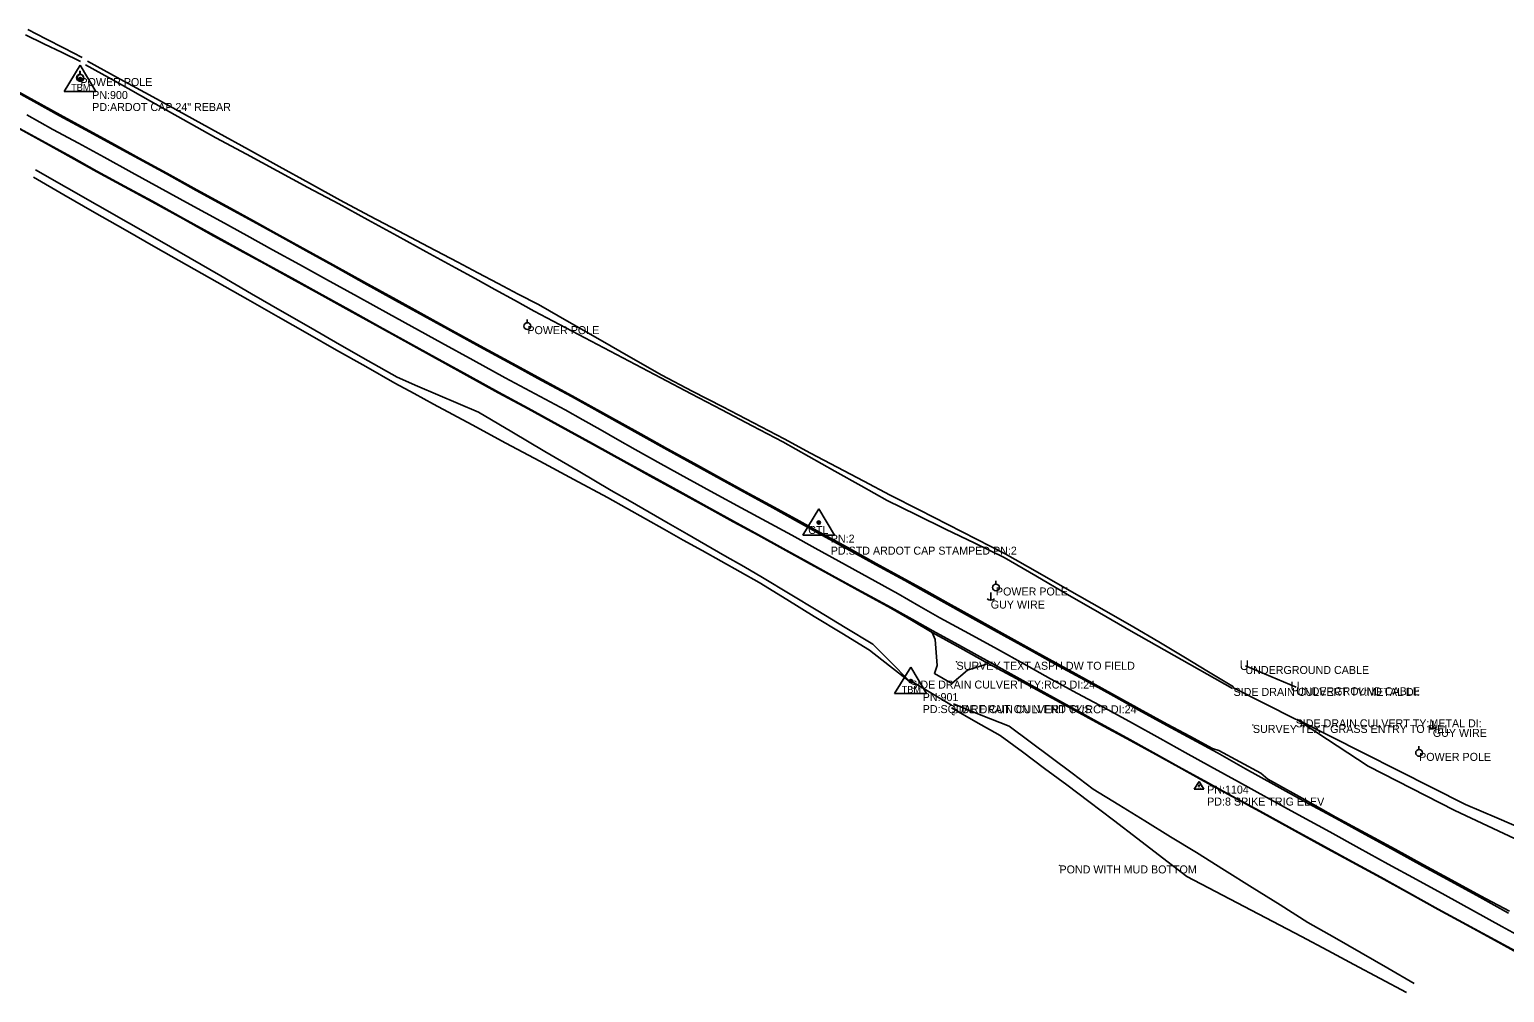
# Model space of a CAD drawing. Extents: x 1411444 to 1458157, y 300965 to 327300.
# Drawn here: x 1453733 to 1454655, y 302804 to 303406 of the extents above; entities that cross this region are included whole.
import ezdxf

# ---------------------------------------------------------------- set-up
doc = ezdxf.new("R2010")
doc.units = 0
for name, color, linetype in [('S_DITCHLINE', 7, 'Continuous'), ('S_DRG_PT_SYM', 7, 'Continuous'), ('S_DRIVEWAY', 7, 'Continuous'), ('S_EDGE_PAVEMENT', 7, 'Continuous'), ('S_MSC_PT_SYM', 7, 'Continuous'), ('S_PAVEMENT_CROWN', 7, 'Continuous'), ('S_PRIMARY_CTL', 7, 'Continuous'), ('S_PRIMARY_CTL_ANNOT', 7, 'Continuous'), ('S_SECONDARY_CTL', 7, 'Continuous'), ('S_SECONDARY_CTL_ANNOT', 7, 'Continuous'), ('S_SHOULDER', 7, 'Continuous'), ('S_SIDE_DRAIN', 7, 'Continuous'), ('S_SIDE_DRAIN_ANNOT', 7, 'Continuous'), ('S_SURVEY_TEXT_ANNOT', 7, 'Continuous'), ('S_UNDERGROUND_CABLE', 7, 'Continuous'), ('S_UNDERGROUND_CABLE_ANNOT', 7, 'Continuous'), ('S_UTILITY_POLE', 7, 'Continuous'), ('S_UTILITY_POLE_ANNOT', 7, 'Continuous'), ('S_UTL_PT_SYM', 7, 'Continuous')]:
    doc.layers.add(name, color=color, linetype=linetype)

msp = doc.modelspace()

# ---------------------------------------------------------------- linework, layer by layer
at = {"layer": 'S_DITCHLINE'}
for points in [[(1453730.77, 303402.44), (1453742.23, 303396.89), (1453753.69, 303391.35), (1453765.15, 303385.8)], [(1453732.25, 303405.79), (1453743.57, 303399.94), (1453754.89, 303394.08), (1453766.21, 303388.22)], [(1453768.3, 303383.8), (1453788.63, 303372.38), (1453808.97, 303360.95), (1453829.3, 303349.52), (1453849.63, 303338.09), (1453868.85, 303327.78), (1453888.08, 303317.46), (1453907.3, 303307.14), (1453926.52, 303296.82), (1453944.74, 303286.85), (1453962.97, 303276.87), (1453981.2, 303266.9), (1453999.42, 303256.92), (1454011.73, 303250.13), (1454024.04, 303243.33), (1454036.36, 303236.53), (1454048.67, 303229.74), (1454068.46, 303219.32), (1454088.25, 303208.9), (1454108.04, 303198.48), (1454127.83, 303188.06), (1454146.88, 303178.05), (1454165.93, 303168.04), (1454184.98, 303158.02), (1454204.03, 303148.01), (1454220.35, 303138.84), (1454236.68, 303129.68), (1454253, 303120.51), (1454269.32, 303111.34), (1454287.57, 303102.45), (1454305.82, 303093.57), (1454324.08, 303084.68), (1454342.33, 303075.79), (1454362.21, 303064.26), (1454382.09, 303052.73), (1454401.97, 303041.19), (1454421.85, 303029.66), (1454437.66, 303020.73), (1454453.47, 303011.8), (1454469.29, 303002.86), (1454485.1, 302993.93)], [(1453769.49, 303386.06), (1453789.92, 303374.85), (1453810.34, 303363.64), (1453830.76, 303352.42), (1453851.18, 303341.21), (1453870.24, 303330.69), (1453889.29, 303320.17), (1453908.34, 303309.66), (1453927.4, 303299.14), (1453945.78, 303289.43), (1453964.17, 303279.71), (1453982.56, 303270), (1454000.95, 303260.29), (1454013.55, 303253.68), (1454026.16, 303247.07), (1454038.76, 303240.47), (1454051.37, 303233.86), (1454070.63, 303222.86), (1454089.88, 303211.85), (1454109.14, 303200.84), (1454128.4, 303189.84), (1454147.51, 303179.85), (1454166.63, 303169.86), (1454185.74, 303159.87), (1454204.85, 303149.88), (1454221.45, 303141.09), (1454238.06, 303132.29), (1454254.66, 303123.5), (1454271.26, 303114.7), (1454289.23, 303105.52), (1454307.2, 303096.35), (1454325.17, 303087.17), (1454343.14, 303077.99), (1454363.24, 303066.57), (1454383.33, 303055.16), (1454403.42, 303043.75), (1454423.51, 303032.33), (1454439.08, 303022.98), (1454454.64, 303013.64), (1454470.21, 303004.29), (1454485.77, 302994.94)], [(1453735.71, 303313.45), (1453754.82, 303302.48), (1453773.93, 303291.52), (1453793.05, 303280.55), (1453812.16, 303269.59), (1453831.32, 303258.72), (1453850.48, 303247.86), (1453869.64, 303237), (1453888.79, 303226.14), (1453907.02, 303215.79), (1453925.24, 303205.44), (1453943.46, 303195.1), (1453961.68, 303184.75), (1453973.74, 303178.24), (1453985.79, 303171.72), (1453997.84, 303165.21), (1454009.9, 303158.69), (1454031.07, 303147.33), (1454052.23, 303135.97), (1454073.4, 303124.6), (1454094.56, 303113.24), (1454106.4, 303106.61), (1454118.23, 303099.98), (1454130.06, 303093.35), (1454141.89, 303086.72), (1454153.72, 303080.09), (1454165.56, 303073.46), (1454177.39, 303066.83), (1454189.22, 303060.2), (1454206.5, 303049.6), (1454223.78, 303039), (1454241.07, 303028.41), (1454258.35, 303017.81), (1454270.74, 303008.15), (1454283.14, 302998.49)], [(1453737.12, 303318.1), (1453756.48, 303307.07), (1453775.84, 303296.04), (1453795.2, 303285), (1453814.56, 303273.97), (1453833.71, 303262.86), (1453852.86, 303251.74), (1453872.01, 303240.63), (1453891.16, 303229.52), (1453909.11, 303219.24), (1453927.07, 303208.97), (1453945.02, 303198.69), (1453962.97, 303188.42), (1453975.72, 303182.95), (1453988.47, 303177.49), (1454001.22, 303172.02), (1454013.97, 303166.56), (1454034.7, 303154.35), (1454055.43, 303142.14), (1454076.16, 303129.94), (1454096.89, 303117.73), (1454108.71, 303110.93), (1454120.53, 303104.13), (1454132.35, 303097.32), (1454144.17, 303090.52), (1454155.98, 303083.72), (1454167.8, 303076.91), (1454179.62, 303070.11), (1454191.44, 303063.31), (1454208.66, 303052.87), (1454225.89, 303042.44), (1454243.11, 303032.01), (1454260.34, 303021.57), (1454271.53, 303010.39), (1454282.73, 302999.21)], [(1454593.78, 302803.91), (1454577.42, 302812.65), (1454561.06, 302821.4), (1454544.71, 302830.14), (1454528.35, 302838.89), (1454510.41, 302848.29), (1454492.48, 302857.69), (1454474.54, 302867.08), (1454456.61, 302876.48), (1454441.31, 302888.18), (1454426.01, 302899.89), (1454410.71, 302911.59), (1454395.41, 302923.29), (1454381.54, 302933.61), (1454367.67, 302943.92), (1454353.8, 302954.24), (1454339.92, 302964.56), (1454324.67, 302973.18), (1454309.41, 302981.81)], [(1454598.74, 302809.49), (1454582.13, 302819.06), (1454565.52, 302828.62), (1454548.91, 302838.19), (1454532.3, 302847.76), (1454514.88, 302858.65), (1454497.46, 302869.54), (1454480.04, 302880.44), (1454462.62, 302891.33), (1454446.47, 302901.26), (1454430.32, 302911.2), (1454414.17, 302921.13), (1454398.02, 302931.07), (1454384.88, 302940.9), (1454371.74, 302950.73), (1454358.6, 302960.56), (1454345.46, 302970.39), (1454328.08, 302977.32), (1454310.71, 302984.26)], [(1454569.93, 302945.43), (1454525.06, 302974.8)], [(1454525.06, 302974.8), (1454630.76, 302921.5)], [(1454569.93, 302945.43), (1454624.14, 302917.64)], [(1454731.72, 302869.5), (1454715.03, 302876.77), (1454698.33, 302884.04), (1454681.64, 302891.31), (1454664.94, 302898.58), (1454644.54, 302908.11), (1454624.14, 302917.64)], [(1454630.76, 302921.5), (1454650.43, 302913.01), (1454670.1, 302904.51), (1454685.4, 302898.04), (1454700.71, 302891.57), (1454716.01, 302885.1), (1454731.32, 302878.63)]]:
    msp.add_lwpolyline(points, dxfattribs=at)
at = {"layer": 'S_DRG_PT_SYM'}
for points in [[(1454283.73, 302998.86), (1454283.73, 302998.91), (1454283.73, 302998.86), (1454283.68, 302998.86), (1454283.73, 302998.86), (1454283.73, 302998.81), (1454283.73, 302998.86), (1454283.78, 302998.86)], [(1454485.8, 302994.28), (1454485.8, 302994.33), (1454485.8, 302994.28), (1454485.75, 302994.28), (1454485.8, 302994.28), (1454485.8, 302994.23), (1454485.8, 302994.28), (1454485.85, 302994.28)], [(1454309.6, 302983.41), (1454309.6, 302983.46), (1454309.6, 302983.41), (1454309.55, 302983.41), (1454309.6, 302983.41), (1454309.6, 302983.36), (1454309.6, 302983.41), (1454309.65, 302983.41)], [(1454524.6, 302974.66), (1454524.6, 302974.71), (1454524.6, 302974.66), (1454524.55, 302974.66), (1454524.6, 302974.66), (1454524.6, 302974.61), (1454524.6, 302974.66), (1454524.65, 302974.66)]]:
    msp.add_lwpolyline(points, dxfattribs=at)
at = {"layer": 'S_DRIVEWAY'}
msp.add_lwpolyline([(1454297.45, 303028.99), (1454299.31, 303024.59), (1454300.64, 303008.39), (1454298.83, 303003.35), (1454309.7, 302996.94), (1454319.42, 303005.34), (1454331.44, 303009.14)], dxfattribs=at)
at = {"layer": 'S_EDGE_PAVEMENT'}
for points in [[(1453719.65, 303369.82), (1453735.88, 303360.87), (1453752.11, 303351.91), (1453768.25, 303343.14), (1453784.38, 303334.37), (1453801.59, 303324.93), (1453818.8, 303315.5), (1453837.53, 303305.22), (1453856.26, 303294.94), (1453872.96, 303285.75), (1453889.65, 303276.55), (1453906.22, 303267.42), (1453922.79, 303258.29), (1453942.43, 303247.35), (1453962.07, 303236.42), (1453994.81, 303218.51), (1454014.73, 303207.52), (1454034.66, 303196.52), (1454053.32, 303186.48), (1454071.98, 303176.44), (1454093.61, 303164.35), (1454115.25, 303152.27), (1454131.83, 303143.06), (1454148.4, 303133.86), (1454165.07, 303124.73), (1454181.74, 303115.6), (1454197.81, 303106.77), (1454213.88, 303097.94), (1454228.94, 303089.55), (1454244, 303081.16), (1454262.16, 303071.26), (1454280.32, 303061.35), (1454293.58, 303053.99), (1454306.85, 303046.63), (1454324.62, 303036.71), (1454342.39, 303026.79), (1454359.5, 303017.38), (1454376.62, 303007.97), (1454392.84, 302999.02), (1454409.06, 302990.07), (1454426.54, 302980.46), (1454444.02, 302970.85), (1454459.86, 302962.23), (1454475.71, 302953.6), (1454493.3, 302943.78), (1454510.9, 302933.96), (1454530.21, 302923.38), (1454549.52, 302912.81), (1454567.97, 302902.72), (1454586.41, 302892.63), (1454604.06, 302882.95), (1454621.7, 302873.27), (1454639.65, 302863.41), (1454657.61, 302853.56)], [(1453727.11, 303344), (1453743.43, 303335.02), (1453759.44, 303326.19), (1453775.45, 303317.35), (1453792.75, 303307.88), (1453810.06, 303298.41), (1453829.53, 303287.76), (1453848.99, 303277.11), (1453864.82, 303268.37), (1453880.65, 303259.63), (1453897.47, 303250.32), (1453914.29, 303241.01), (1453933.24, 303230.52), (1453952.2, 303220.03), (1453987.06, 303200.81), (1454006.73, 303189.98), (1454026.41, 303179.15), (1454044.97, 303169.03), (1454063.54, 303158.91), (1454085.08, 303147.08), (1454106.62, 303135.26), (1454123.16, 303126.14), (1454139.7, 303117.01), (1454156.51, 303107.71), (1454173.33, 303098.42), (1454188.81, 303089.96), (1454204.28, 303081.5), (1454219.6, 303073.02), (1454234.91, 303064.54), (1454253.32, 303054.54), (1454271.74, 303044.54), (1454284.83, 303037.27), (1454297.93, 303030.01), (1454315.66, 303020.15), (1454333.38, 303010.3), (1454350.28, 303000.97), (1454367.18, 302991.64), (1454384.86, 302981.84), (1454402.54, 302972.04), (1454419.08, 302962.99), (1454435.61, 302953.94), (1454451.62, 302945.05), (1454467.63, 302936.17), (1454485, 302926.72), (1454502.37, 302917.26), (1454522.48, 302906.23), (1454542.59, 302895.2), (1454560.17, 302885.6), (1454577.76, 302876), (1454595.75, 302866.03), (1454613.74, 302856.06), (1454631.42, 302846.41), (1454649.09, 302836.76), (1454667.31, 302827.02)]]:
    msp.add_lwpolyline(points, dxfattribs=at)
at = {"layer": 'S_MSC_PT_SYM'}
for points in [[(1454312.66, 303010.62), (1454312.66, 303010.67), (1454312.66, 303010.62), (1454312.61, 303010.62), (1454312.66, 303010.62), (1454312.66, 303010.57), (1454312.66, 303010.62), (1454312.71, 303010.62)], [(1454497.89, 302971.14), (1454497.89, 302971.19), (1454497.89, 302971.14), (1454497.84, 302971.14), (1454497.89, 302971.14), (1454497.89, 302971.09), (1454497.89, 302971.14), (1454497.94, 302971.14)], [(1454377.01, 302883.34), (1454377.01, 302883.39), (1454377.01, 302883.34), (1454376.96, 302883.34), (1454377.01, 302883.34), (1454377.01, 302883.29), (1454377.01, 302883.34), (1454377.06, 302883.34)]]:
    msp.add_lwpolyline(points, dxfattribs=at)
at = {"layer": 'S_PAVEMENT_CROWN'}
msp.add_lwpolyline([(1453731.65, 303352.42), (1453747.93, 303343.37), (1453763.92, 303334.65), (1453779.92, 303325.92), (1453797.13, 303316.5), (1453814.33, 303307.08), (1453833.62, 303296.49), (1453852.91, 303285.9), (1453869.05, 303277.04), (1453885.19, 303268.17), (1453902.01, 303258.89), (1453918.82, 303249.62), (1453938.29, 303238.85), (1453957.77, 303228.08), (1453990.68, 303209.97), (1454010.65, 303199.04), (1454030.62, 303188.11), (1454049.35, 303178.1), (1454068.08, 303168.08), (1454079, 303161.91), (1454089.92, 303155.74), (1454100.84, 303149.57), (1454111.75, 303143.39), (1454127.93, 303134.37), (1454144.11, 303125.34), (1454161.09, 303116.07), (1454178.07, 303106.8), (1454193.85, 303098.27), (1454209.64, 303089.74), (1454224.36, 303081.61), (1454239.08, 303073.48), (1454257.6, 303063.27), (1454276.12, 303053.06), (1454289.2, 303045.59), (1454302.28, 303038.11), (1454320.28, 303028.31), (1454338.27, 303018.5), (1454338.23, 303018.53), (1454354.77, 303009.26), (1454371.32, 302999.99), (1454388.25, 302990.88), (1454405.18, 302981.76), (1454422.57, 302972.17), (1454439.96, 302962.58), (1454455.64, 302953.9), (1454471.32, 302945.21), (1454488.98, 302935.53), (1454506.64, 302925.84), (1454526.35, 302915.05), (1454546.06, 302904.26), (1454564.23, 302894.21), (1454582.4, 302884.16), (1454600.21, 302874.45), (1454618.02, 302864.75), (1454635.75, 302855.01), (1454653.49, 302845.26), (1454671.84, 302835.16)], dxfattribs=at)
at = {"layer": 'S_PRIMARY_CTL'}
for p, q in [((1453764.95, 303383.55), (1453754.92, 303367.04)), ((1453764.95, 303383.55), (1453774.77, 303367.04)), ((1453754.92, 303367.04), (1453774.77, 303367.04)), ((1454226.56, 303106.27), (1454216.53, 303089.76)), ((1454226.56, 303106.27), (1454236.38, 303089.76)), ((1454216.53, 303089.76), (1454236.38, 303089.76)), ((1454284.01, 303007.24), (1454273.97, 302990.73)), ((1454284.01, 303007.24), (1454293.83, 302990.73)), ((1454273.97, 302990.73), (1454293.83, 302990.73))]:
    msp.add_line(p, q, dxfattribs=at)
for centre, radius in [((1453764.95, 303374.85), 1.04), ((1453764.95, 303374.85), 0.609), ((1453764.95, 303374.85), 0.344), ((1454226.56, 303097.57), 1.04), ((1454226.56, 303097.57), 0.609), ((1454226.56, 303097.57), 0.344), ((1454284.01, 302998.54), 1.04), ((1454284.01, 302998.54), 0.609), ((1454284.01, 302998.54), 0.344)]:
    msp.add_circle(centre, radius, dxfattribs=at)
at = {"layer": 'S_SECONDARY_CTL'}
for p, q in [((1454464.29, 302935.85), (1454461.28, 302930.9)), ((1454464.29, 302935.85), (1454467.24, 302930.9)), ((1454461.28, 302930.9), (1454467.24, 302930.9))]:
    msp.add_line(p, q, dxfattribs=at)
for radius in [0.311, 0.183, 0.103]:
    msp.add_circle((1454464.29, 302933.24), radius, dxfattribs=at)
at = {"layer": 'S_SHOULDER'}
for points in [[(1453719.96, 303370.38), (1453736.16, 303361.41), (1453752.37, 303352.44), (1453768.5, 303343.66), (1453784.62, 303334.88), (1453801.82, 303325.41), (1453819.01, 303315.94), (1453837.78, 303305.65), (1453856.56, 303295.36), (1453873.19, 303286.16), (1453889.81, 303276.95), (1453906.4, 303267.88), (1453922.99, 303258.8), (1453942.69, 303247.96), (1453962.39, 303237.12), (1453995.11, 303218.9), (1454014.98, 303208.13), (1454034.84, 303197.35), (1454053.65, 303187.06), (1454072.47, 303176.77), (1454093.89, 303164.88), (1454115.31, 303152.99), (1454132.05, 303143.76), (1454148.79, 303134.54), (1454165.85, 303125.18), (1454182.91, 303115.83), (1454198.63, 303107.27), (1454214.35, 303098.71), (1454229.34, 303090.44), (1454244.33, 303082.18), (1454262.51, 303072.11), (1454280.69, 303062.05), (1454294.03, 303054.66), (1454307.38, 303047.27), (1454325.17, 303037.37), (1454342.96, 303027.47), (1454359.95, 303018.07), (1454376.95, 303008.67), (1454393.22, 302999.72), (1454409.5, 302990.76), (1454426.9, 302981.21), (1454444.31, 302971.66), (1454458.49, 302964.06), (1454472.67, 302956.47), (1454476.68, 302955.24), (1454489.78, 302948.14), (1454502.87, 302941.04), (1454507.13, 302937.26), (1454511.36, 302934.92), (1454530.59, 302924.24), (1454549.82, 302913.55), (1454568.36, 302903.49), (1454586.89, 302893.42), (1454604.54, 302883.78), (1454622.18, 302874.13), (1454640.22, 302864.4), (1454658.26, 302854.67)], [(1453726.96, 303343.7), (1453743.32, 303334.72), (1453759.34, 303325.81), (1453775.37, 303316.89), (1453792.61, 303307.49), (1453809.85, 303298.09), (1453829.21, 303287.37), (1453848.57, 303276.66), (1453864.49, 303267.95), (1453880.42, 303259.24), (1453897.32, 303249.92), (1453914.21, 303240.59), (1453933.11, 303230.16), (1453952, 303219.72), (1454026.15, 303178.78), (1454044.85, 303168.66), (1454063.55, 303158.55), (1454085.04, 303146.6), (1454106.53, 303134.65), (1454123, 303125.65), (1454139.46, 303116.65), (1454156.27, 303107.41), (1454173.08, 303098.17), (1454188.62, 303089.65), (1454204.16, 303081.14), (1454219.49, 303072.72), (1454234.82, 303064.3), (1454253.18, 303054.21), (1454271.55, 303044.12), (1454284.51, 303036.55), (1454297.47, 303028.97), (1454315, 303019.26), (1454332.52, 303009.56), (1454349.95, 303000.09), (1454367.38, 302990.61), (1454384.8, 302981.14), (1454402.23, 302971.66), (1454418.83, 302962.66), (1454435.44, 302953.66), (1454451.53, 302944.72), (1454467.62, 302935.77), (1454484.92, 302926.41), (1454502.21, 302917.05), (1454522.25, 302906.02), (1454542.29, 302895), (1454559.97, 302885.4), (1454577.66, 302875.8), (1454595.71, 302865.82), (1454613.77, 302855.84), (1454631.36, 302846.18), (1454648.96, 302836.53), (1454667.08, 302826.6)]]:
    msp.add_lwpolyline(points, dxfattribs=at)
at = {"layer": 'S_SIDE_DRAIN'}
for p, q in [((1454283.73, 302998.86), (1454309.6, 302983.41)), ((1454485.8, 302994.28), (1454524.6, 302974.66))]:
    msp.add_line(p, q, dxfattribs=at)
at = {"layer": 'S_UNDERGROUND_CABLE'}
msp.add_line((1454493.23, 303007.99), (1454524.96, 302994.7), dxfattribs=at)
at = {"layer": 'S_UTILITY_POLE'}
for p, q in [((1453764.71, 303377.75), (1453764.71, 303379.86)), ((1453764.98, 303377.6), (1453764.98, 303379.71)), ((1454044.33, 303222.53), (1454044.33, 303224.64)), ((1454337.16, 303059.19), (1454337.16, 303061.3)), ((1454334.03, 303053.83), (1454334.03, 303049.1)), ((1454610.32, 302973.62), (1454610.32, 302968.89)), ((1454601.65, 302955.82), (1454601.65, 302957.93))]:
    msp.add_line(p, q, dxfattribs=at)
for centre in [(1453764.84, 303375.61), (1453765.1, 303375.46), (1454044.45, 303220.39), (1454337.29, 303057.05), (1454601.78, 302953.68)]:
    msp.add_circle(centre, 2.13, dxfattribs=at)
for centre in [(1454334.09, 303052.52), (1454610.38, 302972.32)]:
    msp.add_arc(centre, 3.41, 226.39718, 313.60282, dxfattribs=at)

# ---------------------------------------------------------------- texts
at = {"layer": 'S_PRIMARY_CTL'}
for s, height, p in [('TBM', 4.287, (1453759.3, 303367.46)), ('CTL', 5, (1454219.97, 303090.49)), ('TBM', 4.287, (1454278.36, 302991.15))]:
    msp.add_text(s, height=height, rotation=360, dxfattribs=at).set_placement(p)
at = {"layer": 'S_PRIMARY_CTL_ANNOT'}
for s, p in [('PN:900', (1453772.45, 303362.35)), ('PD:ARDOT CAP 24" REBAR', (1453772.45, 303354.85)), ('PN:2', (1454234.06, 303085.07)), ('PD:STD ARDOT CAP STAMPED PN:2', (1454234.06, 303077.57)), ('PN:901', (1454291.51, 302986.04)), ('PD:SQUARE CUT ON N END CUS', (1454291.51, 302978.54))]:
    msp.add_text(s, height=5, dxfattribs=at).set_placement(p)
at = {"layer": 'S_SECONDARY_CTL'}
msp.add_text('TV', height=1.5, rotation=360, dxfattribs=at).set_placement((1454463.09, 302931.23))
at = {"layer": 'S_SECONDARY_CTL_ANNOT'}
for s, p in [('PN:1104', (1454469.29, 302928.24)), ('PD:8 SPIKE TRIG ELEV', (1454469.29, 302920.74))]:
    msp.add_text(s, height=5, dxfattribs=at).set_placement(p)
at = {"layer": 'S_SIDE_DRAIN_ANNOT'}
for s, p in [('SIDE DRAIN CULVERT TY:RCP DI:24', (1454283.73, 302993.86)), ('SIDE DRAIN CULVERT TY:METAL DI:', (1454485.8, 302989.28)), ('SIDE DRAIN CULVERT TY:RCP DI:24', (1454309.6, 302978.41)), ('SIDE DRAIN CULVERT TY:METAL DI:', (1454524.6, 302969.66))]:
    msp.add_text(s, height=5, dxfattribs=at).set_placement(p)
at = {"layer": 'S_SURVEY_TEXT_ANNOT'}
for s, p in [('SURVEY TEXT ASPH DW TO FIELD', (1454312.66, 303005.62)), ('SURVEY TEXT GRASS ENTRY TO FIEL', (1454497.89, 302966.14)), ('POND WITH MUD BOTTOM', (1454377.01, 302878.34))]:
    msp.add_text(s, height=5, dxfattribs=at).set_placement(p)
at = {"layer": 'S_UNDERGROUND_CABLE_ANNOT'}
for p in [(1454493.23, 303002.99), (1454524.96, 302989.7)]:
    msp.add_text('UNDERGROUND CABLE', height=5, dxfattribs=at).set_placement(p)
at = {"layer": 'S_UTILITY_POLE_ANNOT'}
for s, p in [('POWER POLE', (1453765.1, 303370.46)), ('POWER POLE', (1454044.45, 303215.39)), ('POWER POLE', (1454337.29, 303052.05)), ('GUY WIRE', (1454334.05, 303043.88)), ('GUY WIRE', (1454610.33, 302963.68)), ('POWER POLE', (1454601.78, 302948.68))]:
    msp.add_text(s, height=5, dxfattribs=at).set_placement(p)
at = {"layer": 'S_UTL_PT_SYM'}
for p in [(1454489.6, 303005.45), (1454521.33, 302992.15)]:
    msp.add_text('U', height=6, rotation=360, dxfattribs=at).set_placement(p)

doc.saveas('drawing.dxf')
